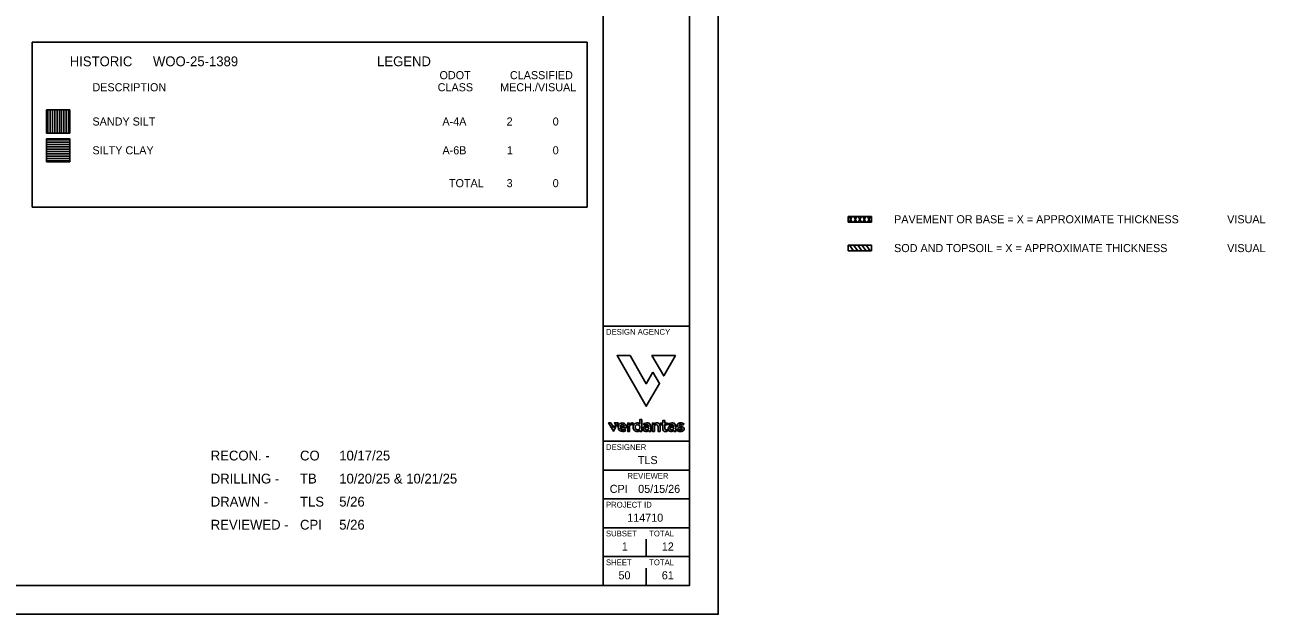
# Model space of a CAD drawing. Extents: x -59 to 43, y 0 to 22.
# Drawn here: x 21.96 to 43.49, y 0 to 10.23 of the extents above; entities that cross this region are included whole.
import ezdxf

# ---------------------------------------------------------------- set-up
doc = ezdxf.new("R2010")
doc.units = 0
for name, color, linetype in [('Default', 7, 'Continuous'), ('GT_Project_Soil_Layers', 7, 'Continuous'), ('SH_Border', 7, 'Continuous'), ('SH_Cut_Line', 7, 'Continuous'), ('SH_Data', 7, 'Continuous'), ('SH_Text', 7, 'Continuous')]:
    doc.layers.add(name, color=color, linetype=linetype)

msp = doc.modelspace()

# ---------------------------------------------------------------- linework, layer by layer
at = {"layer": 'Default'}
for p, q in [((22.342, 8.751), (22.342, 8.751)), ((22.362, 8.351), (22.362, 8.751)), ((22.402, 8.351), (22.402, 8.751)), ((22.442, 8.351), (22.442, 8.751)), ((22.482, 8.351), (22.482, 8.751)), ((22.522, 8.351), (22.522, 8.751)), ((22.562, 8.351), (22.562, 8.751)), ((22.602, 8.351), (22.602, 8.751)), ((22.642, 8.351), (22.642, 8.751)), ((22.682, 8.351), (22.682, 8.751)), ((22.722, 8.351), (22.722, 8.751)), ((22.742, 8.751), (22.742, 8.751)), ((22.342, 8.351), (22.342, 8.351)), ((22.342, 8.251), (22.342, 8.251)), ((22.342, 8.231), (22.742, 8.231)), ((22.342, 8.191), (22.742, 8.191)), ((22.742, 8.351), (22.742, 8.351)), ((22.742, 8.251), (22.742, 8.251)), ((22.342, 8.151), (22.742, 8.151)), ((22.342, 8.111), (22.742, 8.111)), ((22.342, 8.071), (22.742, 8.071)), ((22.342, 8.031), (22.742, 8.031)), ((22.342, 7.991), (22.742, 7.991)), ((22.342, 7.951), (22.742, 7.951)), ((22.342, 7.911), (22.742, 7.911)), ((22.342, 7.871), (22.742, 7.871)), ((22.342, 7.851), (22.342, 7.851)), ((22.342, 7.851), (22.342, 7.851)), ((22.342, 7.849), (22.342, 7.849)), ((22.742, 7.851), (22.742, 7.851)), ((22.76, 7.849), (22.76, 7.849))]:
    msp.add_line(p, q, dxfattribs=at)
at = {"layer": 'GT_Project_Soil_Layers'}
for p, q in [((36.27, 6.904), (36.323, 6.804)), ((36.27, 6.804), (36.323, 6.904)), ((36.35, 6.804), (36.403, 6.904)), ((36.35, 6.904), (36.403, 6.804)), ((36.43, 6.904), (36.483, 6.804)), ((36.43, 6.804), (36.483, 6.904)), ((36.51, 6.904), (36.563, 6.804)), ((36.51, 6.804), (36.563, 6.904)), ((36.59, 6.904), (36.643, 6.804)), ((36.59, 6.804), (36.643, 6.904)), ((36.275, 6.404), (36.347, 6.304)), ((36.347, 6.404), (36.42, 6.304)), ((36.42, 6.404), (36.493, 6.304)), ((36.493, 6.404), (36.565, 6.304)), ((36.565, 6.404), (36.638, 6.304))]:
    msp.add_line(p, q, dxfattribs=at)
at = {"layer": 'SH_Border'}
for p, q in [((32, 0.5), (32, 21.5)), ((32, 5), (33.5, 5)), ((32, 3), (33.5, 3)), ((32, 2.5), (33.5, 2.5)), ((32, 2), (33.5, 2)), ((32, 1.5), (33.5, 1.5)), ((32, 1), (33.5, 1))]:
    msp.add_line(p, q, dxfattribs=at)
msp.add_lwpolyline([(1.5, 21.5), (33.5, 21.5), (33.5, 0.5), (1.5, 0.5)], close=True, dxfattribs=at)
at = {"layer": 'SH_Cut_Line'}
msp.add_lwpolyline([(0, 0), (34, 0), (34, 22), (0, 22)], close=True, dxfattribs=at)
at = {"layer": 'SH_Data'}
for p, q in [((22.092, 7.066), (22.092, 9.93)), ((31.724, 9.93), (22.092, 9.93)), ((31.724, 7.066), (31.724, 9.93)), ((31.724, 7.066), (22.092, 7.066)), ((36.256, 6.804), (36.256, 6.904)), ((36.256, 6.904), (36.656, 6.904)), ((36.656, 6.804), (36.656, 6.904)), ((36.256, 6.804), (36.656, 6.804)), ((36.256, 6.304), (36.256, 6.404)), ((36.256, 6.404), (36.656, 6.404)), ((36.256, 6.304), (36.656, 6.304)), ((36.656, 6.304), (36.656, 6.404)), ((32.75, 4), (32.75, 4)), ((32.75, 1), (32.75, 1.3)), ((32.375, 0.675), (32.375, 0.675)), ((32.75, 0.5), (32.75, 0.8))]:
    msp.add_line(p, q, dxfattribs=at)
for points in [[(22.342, 8.351), (22.742, 8.351), (22.742, 8.751), (22.342, 8.751)], [(22.342, 7.851), (22.742, 7.851), (22.742, 8.251), (22.342, 8.251)]]:
    msp.add_lwpolyline(points, close=True, dxfattribs=at)
at = {"layer": 'SH_Text'}
for p, q in [((32.292, 3.234), (32.407, 3.234)), ((32.373, 3.256), (32.293, 3.256)), ((32.509, 3.288), (32.525, 3.316)), ((32.637, 3.267), (32.637, 3.222)), ((32.712, 3.311), (32.703, 3.308)), ((32.793, 3.263), (32.793, 3.251)), ((32.793, 3.232), (32.793, 3.215)), ((33.146, 3.311), (33.137, 3.308)), ((33.227, 3.263), (33.227, 3.251)), ((33.227, 3.232), (33.227, 3.215)), ((33.332, 3.233), (33.347, 3.23)), ((33.364, 3.255), (33.34, 3.26)), ((33.385, 3.28), (33.402, 3.304)), ((32.396, 3.189), (32.379, 3.213)), ((33.119, 3.178), (33.107, 3.204)), ((33.295, 3.218), (33.276, 3.194))]:
    msp.add_line(p, q, dxfattribs=at)
for points in [[(32.866, 4.201), (32.75, 4), (32.468, 4.488), (32.243, 4.488), (32.75, 3.61), (32.979, 4.006)], [(32.199, 3.272), (32.18, 3.239), (32.133, 3.32), (32.095, 3.32), (32.18, 3.174), (32.218, 3.24)], [(32.23, 3.261), (32.196, 3.32), (32.264, 3.32)]]:
    msp.add_lwpolyline(points, close=True, dxfattribs=at)
for points in [[(32.866, 4.201), (32.75, 4), (32.468, 4.488), (32.243, 4.488), (32.75, 3.61), (32.979, 4.006), (32.866, 4.201)], [(33.257, 4.488), (32.848, 4.488), (33.053, 4.134), (33.257, 4.488)], [(32.199, 3.272), (32.18, 3.239), (32.133, 3.32), (32.095, 3.32), (32.18, 3.174), (32.218, 3.24), (32.199, 3.272)], [(32.264, 3.32), (32.196, 3.32), (32.23, 3.261), (32.264, 3.32)], [(32.292, 3.234), (32.407, 3.234)], [(32.293, 3.256), (32.373, 3.256)], [(32.458, 3.286), (32.458, 3.316), (32.427, 3.316), (32.427, 3.173), (32.46, 3.173), (32.46, 3.268)], [(32.458, 3.286), (32.458, 3.316), (32.427, 3.316), (32.427, 3.173), (32.46, 3.173), (32.46, 3.268)], [(32.509, 3.288), (32.525, 3.316)], [(32.637, 3.297), (32.637, 3.377), (32.671, 3.377), (32.671, 3.173), (32.64, 3.173), (32.64, 3.199)], [(32.64, 3.199), (32.64, 3.173), (32.671, 3.173), (32.671, 3.377), (32.637, 3.377), (32.637, 3.297)], [(32.637, 3.267), (32.637, 3.222)], [(32.712, 3.311), (32.703, 3.308)], [(32.703, 3.308), (32.714, 3.281), (32.721, 3.284)], [(32.703, 3.308), (32.714, 3.281), (32.721, 3.284)], [(32.793, 3.263), (32.793, 3.251)], [(32.793, 3.215), (32.793, 3.232)], [(32.796, 3.196), (32.796, 3.173), (32.827, 3.173), (32.827, 3.267)], [(32.796, 3.196), (32.796, 3.173), (32.827, 3.173), (32.827, 3.267)], [(32.887, 3.288), (32.887, 3.316), (32.856, 3.316), (32.856, 3.173), (32.89, 3.173), (32.89, 3.269)], [(32.887, 3.288), (32.887, 3.316), (32.856, 3.316), (32.856, 3.173), (32.89, 3.173), (32.89, 3.269)], [(32.954, 3.257), (32.954, 3.173), (32.988, 3.173), (32.988, 3.267)], [(32.954, 3.257), (32.954, 3.173), (32.988, 3.173), (32.988, 3.267)], [(33.07, 3.226), (33.07, 3.287), (33.116, 3.287), (33.116, 3.316), (33.07, 3.316), (33.07, 3.36), (33.036, 3.36), (33.036, 3.316), (32.991, 3.316), (33.009, 3.287), (33.036, 3.287), (33.036, 3.22)], [(33.07, 3.226), (33.07, 3.287), (33.116, 3.287), (33.116, 3.316), (33.07, 3.316), (33.07, 3.36), (33.036, 3.36), (33.036, 3.316), (32.991, 3.316), (33.009, 3.287), (33.036, 3.287), (33.036, 3.22)], [(33.146, 3.311), (33.137, 3.308)], [(33.137, 3.308), (33.148, 3.281), (33.155, 3.284)], [(33.137, 3.308), (33.148, 3.281), (33.155, 3.284)], [(33.227, 3.263), (33.227, 3.251)], [(33.227, 3.215), (33.227, 3.232)], [(33.23, 3.196), (33.23, 3.173), (33.261, 3.173), (33.261, 3.267)], [(33.23, 3.196), (33.23, 3.173), (33.261, 3.173), (33.261, 3.267)], [(33.332, 3.233), (33.347, 3.23)], [(33.364, 3.255), (33.34, 3.26)], [(33.383, 3.281), (33.385, 3.28)], [(33.385, 3.28), (33.402, 3.304), (33.401, 3.304)], [(32.396, 3.189), (32.379, 3.213)], [(33.119, 3.178), (33.107, 3.204)], [(33.296, 3.216), (33.295, 3.218), (33.276, 3.194), (33.279, 3.192)]]:
    msp.add_lwpolyline(points, dxfattribs=at)
for centre, radius, start, end in [((32.333, 3.245), 0.0747, 351.0446, 190.2577), ((32.333, 3.245), 0.0747, 351.0446, 190.2577), ((32.342, 3.255), 0.0854, 195.6668, 309.3699), ((32.342, 3.255), 0.0854, 195.6668, 309.3699), ((32.343, 3.253), 0.054, 200.9232, 312.7391), ((32.343, 3.253), 0.054, 200.9232, 312.7391), ((32.333, 3.25), 0.0407, 8.8378, 171.1622), ((32.333, 3.25), 0.0407, 8.8378, 171.1622), ((32.504, 3.274), 0.0471, 62.6524, 165.2929), ((32.504, 3.274), 0.0471, 62.6524, 165.2929), ((32.496, 3.249), 0.0409, 72.1384, 152.0408), ((32.496, 3.249), 0.0409, 72.1384, 152.0408), ((32.595, 3.245), 0.075, 92.7719, 272.9779), ((32.595, 3.245), 0.075, 92.7719, 272.9779), ((32.6, 3.245), 0.0446, 86.4529, 275.055), ((32.6, 3.245), 0.0446, 86.4529, 275.055), ((32.593, 3.266), 0.0536, 34.2843, 91.2723), ((32.593, 3.266), 0.0536, 34.2843, 91.2723), ((32.599, 3.246), 0.0439, 29.9007, 85.5797), ((32.599, 3.246), 0.0439, 29.9007, 85.5797), ((32.736, 3.216), 0.0444, 111.6764, 249.7268), ((32.736, 3.216), 0.0444, 111.6764, 249.7268), ((32.763, 3.171), 0.149, 90.9467, 109.8354), ((32.763, 3.171), 0.149, 90.9467, 109.8354), ((32.751, 3.182), 0.0814, 58.3497, 112.4708), ((32.751, 3.182), 0.0814, 58.3497, 112.4708), ((32.762, 3.177), 0.114, 91.6616, 110.8714), ((32.762, 3.177), 0.114, 91.6616, 110.8714), ((32.747, 3.218), 0.021, 92.327, 265.3778), ((32.747, 3.218), 0.021, 92.327, 265.3778), ((32.759, 3.162), 0.0786, 63.8372, 98.8746), ((32.759, 3.162), 0.0786, 63.8372, 98.8746), ((32.758, 3.242), 0.0486, 73.2522, 89.9971), ((32.758, 3.242), 0.0486, 73.2522, 89.9971), ((32.762, 3.224), 0.0962, 70.8128, 90.9317), ((32.762, 3.224), 0.0962, 70.8128, 90.9317), ((32.765, 3.262), 0.0281, 2.9671, 75.223), ((32.765, 3.262), 0.0281, 2.9671, 75.223), ((32.779, 3.269), 0.0479, 358.076, 72.8642), ((32.779, 3.269), 0.0479, 358.076, 72.8642), ((32.936, 3.268), 0.0527, 358.9896, 156.9111), ((32.936, 3.268), 0.0527, 358.9896, 156.9111), ((32.922, 3.254), 0.0358, 90.3466, 154.9113), ((32.922, 3.254), 0.0358, 90.3466, 154.9113), ((32.924, 3.257), 0.0325, 47.3049, 92.9688), ((32.924, 3.257), 0.0325, 47.3049, 92.9688), ((32.922, 3.259), 0.0325, 356.9739, 42.7421), ((32.922, 3.259), 0.0325, 356.9739, 42.7421), ((33.17, 3.216), 0.0444, 111.6764, 249.7268), ((33.17, 3.216), 0.0444, 111.6764, 249.7268), ((33.197, 3.171), 0.149, 90.9467, 109.8354), ((33.197, 3.171), 0.149, 90.9467, 109.8354), ((33.184, 3.182), 0.0814, 58.3497, 112.4708), ((33.184, 3.182), 0.0814, 58.3497, 112.4708), ((33.196, 3.177), 0.114, 91.6616, 110.8714), ((33.196, 3.177), 0.114, 91.6616, 110.8714), ((33.181, 3.218), 0.021, 92.327, 265.3778), ((33.181, 3.218), 0.021, 92.327, 265.3778), ((33.192, 3.162), 0.0786, 63.8372, 98.8746), ((33.192, 3.162), 0.0786, 63.8372, 98.8746), ((33.192, 3.242), 0.0486, 73.2522, 89.9971), ((33.192, 3.242), 0.0486, 73.2522, 89.9971), ((33.196, 3.224), 0.0962, 70.8128, 90.9317), ((33.196, 3.224), 0.0962, 70.8128, 90.9317), ((33.199, 3.262), 0.0281, 2.9671, 75.223), ((33.199, 3.262), 0.0281, 2.9671, 75.223), ((33.213, 3.269), 0.0479, 358.076, 72.8642), ((33.213, 3.269), 0.0479, 358.076, 72.8642), ((33.319, 3.276), 0.0344, 148.9453, 227.6829), ((33.319, 3.276), 0.0344, 148.9453, 227.6829), ((33.332, 3.267), 0.0503, 113.3692, 147.807), ((33.332, 3.267), 0.0503, 113.3692, 147.807), ((33.347, 3.311), 0.0789, 230.1259, 259.7023), ((33.347, 3.311), 0.0789, 230.1259, 259.7023), ((33.346, 3.235), 0.0854, 89.0109, 113.56), ((33.347, 3.233), 0.0867, 89.2017, 113.3692), ((33.329, 3.276), 0.0111, 134.7822, 240.4366), ((33.329, 3.276), 0.0111, 134.7822, 240.4366), ((33.339, 3.265), 0.0251, 103.8561, 133.7191), ((33.339, 3.265), 0.0251, 103.8561, 133.7191), ((33.352, 3.321), 0.0614, 242.9002, 259.3831), ((33.352, 3.321), 0.0614, 242.9002, 259.3831), ((33.347, 3.239), 0.0526, 89.0539, 105.6921), ((33.347, 3.239), 0.0526, 89.0539, 105.6921), ((33.336, 3.16), 0.0712, 68.1863, 80.6328), ((33.336, 3.16), 0.0712, 68.1863, 80.6328), ((33.348, 3.221), 0.0985, 57.2233, 89.842), ((33.348, 3.222), 0.0979, 56.3984, 89.8856), ((33.346, 3.221), 0.0711, 58.1233, 88.1135), ((33.346, 3.221), 0.071, 56.2397, 88.1242), ((33.342, 3.16), 0.0972, 64.0447, 77.2149), ((33.342, 3.16), 0.0972, 64.0447, 77.2149), ((33.369, 3.215), 0.0369, 322.7092, 64.2166), ((33.369, 3.214), 0.037, 322.8811, 64.0447), ((32.594, 3.22), 0.0503, 275.3084, 334.5252), ((32.594, 3.22), 0.0503, 275.3084, 334.5252), ((32.599, 3.244), 0.0441, 276.0666, 330.041), ((32.599, 3.244), 0.0441, 276.0666, 330.041), ((32.744, 3.234), 0.0643, 248.2774, 323.7949), ((32.744, 3.234), 0.0643, 248.2774, 323.7949), ((32.755, 3.244), 0.0478, 258.1247, 322.3678), ((32.755, 3.244), 0.0478, 258.1247, 322.3678), ((33.084, 3.218), 0.0482, 177.8641, 271.6213), ((33.084, 3.218), 0.0482, 177.8641, 271.6213), ((33.094, 3.224), 0.0236, 175.0692, 266.3548), ((33.094, 3.224), 0.0236, 175.0692, 266.3548), ((33.086, 3.24), 0.0704, 269.5424, 298.2495), ((33.086, 3.24), 0.0704, 269.5424, 298.2495), ((33.091, 3.232), 0.0324, 271.8638, 299.9651), ((33.091, 3.232), 0.0324, 271.8638, 299.9651), ((33.178, 3.234), 0.0643, 248.2774, 323.7949), ((33.178, 3.234), 0.0643, 248.2774, 323.7949), ((33.189, 3.244), 0.0478, 258.1247, 322.3678), ((33.189, 3.244), 0.0478, 258.1247, 322.3678), ((33.34, 3.266), 0.0958, 227.8814, 270.5651), ((33.34, 3.267), 0.0971, 230.5166, 270.4341), ((33.344, 3.268), 0.0698, 225.2875, 267.0077), ((33.344, 3.268), 0.0699, 227.363, 266.9244), ((33.343, 3.247), 0.0491, 267.0077, 296.3112), ((33.343, 3.247), 0.0491, 267.0077, 296.3112), ((33.343, 3.259), 0.0897, 269.0192, 292.9257), ((33.342, 3.26), 0.0904, 269.1171, 292.8278), ((33.359, 3.214), 0.0124, 296.9165, 73.602), ((33.359, 3.214), 0.0124, 296.9165, 73.602), ((33.357, 3.226), 0.0533, 292.8278, 320.7157), ((33.357, 3.226), 0.0533, 292.8278, 320.7157)]:
    msp.add_arc(centre, radius, start, end, dxfattribs=at)

# ---------------------------------------------------------------- texts
at = {"layer": 'SH_Data'}
for s, height, p in [('DESIGN AGENCY', 0.1, (32.05, 4.85)), ('DESIGNER', 0.1, (32.05, 2.85)), ('TLS', 0.14, (32.603, 2.605)), ('REVIEWER', 0.1, (32.422, 2.35)), ('CPI', 0.14, (32.116, 2.105)), ('05/15/26', 0.14, (32.609, 2.105)), ('PROJECT ID', 0.1, (32.05, 1.85)), ('SUBSET', 0.1, (32.05, 1.35)), ('TOTAL', 0.1, (32.8, 1.35)), ('1', 0.14, (32.325, 1.105)), ('12', 0.14, (33.019, 1.105)), ('SHEET', 0.1, (32.05, 0.85)), ('TOTAL', 0.1, (32.8, 0.85)), ('50', 0.14, (32.267, 0.605)), ('61', 0.14, (33.019, 0.605))]:
    msp.add_text(s, height=height, dxfattribs=at).set_placement(p)
at = {"layer": 'SH_Text'}
for s, height, p in [('HISTORIC  ', 0.17, (22.743, 9.51)), ('WOO-25-1389', 0.17, (24.187, 9.51)), ('LEGEND', 0.17, (28.077, 9.51)), ('ODOT', 0.14, (29.161, 9.285)), ('CLASSIFIED', 0.14, (30.383, 9.285)), ('DESCRIPTION', 0.14, (23.137, 9.075)), ('CLASS', 0.14, (29.129, 9.075)), ('MECH./VISUAL', 0.14, (30.213, 9.075)), ('SANDY SILT', 0.14, (23.137, 8.481)), ('A-4A', 0.14, (29.211, 8.481)), ('2', 0.14, (30.325, 8.481)), ('0', 0.14, (31.125, 8.481)), ('SILTY CLAY', 0.14, (23.137, 7.981)), ('A-6B', 0.14, (29.212, 7.981)), ('1', 0.14, (30.331, 7.981)), ('0', 0.14, (31.125, 7.981)), ('   TOTAL   ', 0.14, (29.169, 7.411)), ('3', 0.14, (30.325, 7.411)), ('0', 0.14, (31.125, 7.411)), ('PAVEMENT OR BASE = X = APPROXIMATE THICKNESS', 0.14, (37.051, 6.784)), ('   VISUAL  ', 0.14, (42.676, 6.784)), ('SOD AND TOPSOIL = X = APPROXIMATE THICKNESS', 0.14, (37.051, 6.284)), ('   VISUAL  ', 0.14, (42.676, 6.284)), ('RECON. -', 0.17, (25.19, 2.668)), ('CO', 0.17, (26.74, 2.668)), ('10/17/25', 0.17, (27.42, 2.668)), ('DRILLING -', 0.17, (25.19, 2.268)), ('TB', 0.17, (26.74, 2.268)), ('10/20/25 & 10/21/25', 0.17, (27.42, 2.268)), ('DRAWN -', 0.17, (25.19, 1.868)), ('TLS', 0.17, (26.74, 1.868)), ('5/26', 0.17, (27.42, 1.868)), ('114710', 0.14, (32.419, 1.605)), ('REVIEWED -', 0.17, (25.19, 1.468)), ('CPI', 0.17, (26.74, 1.468)), ('5/26', 0.17, (27.42, 1.468))]:
    msp.add_text(s, height=height, dxfattribs=at).set_placement(p)

doc.saveas('drawing.dxf')
